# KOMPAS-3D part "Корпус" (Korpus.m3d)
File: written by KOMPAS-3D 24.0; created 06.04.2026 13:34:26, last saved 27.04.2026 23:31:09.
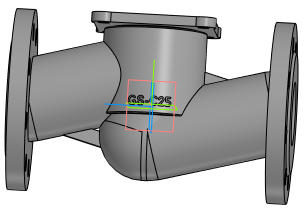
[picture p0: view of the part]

Document properties: Автор: R2D2; Полное имя файла: C:\Работа\ГОТОВЫЕ ИСХОДНИКИ\VSO2130M-F-S Клапан запорный сальниковый DN.ru Ду15-100 Ру40\исходные материалы\DN65\Korpus.m3d

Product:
- Body: Труба / Нестандартная труба / L = 186.9 мм  | qty 1  | 2 such rows
    Материал: Нестандартная труба (density 7856 kg/m3)
    Масса: 24.169128
    Раздел спецификации: Детали
    Примечание: 8,33 кг
    additional columns: Pipeline; 0.085; 0; 0; 0.002; 0.18688; true; 0.04
- Body: Тело 4  | qty 1
    Материал: Нестандартная труба (density 7856 kg/m3)
    Масса: 24.169128
- Body: Тело 5  | qty 1
    Материал: Нестандартная труба (density 7856 kg/m3)
    Масса: 24.169128
- Body: Тело 8  | qty 1
    Материал: Нестандартная труба (density 7856 kg/m3)
    Масса: 24.169128
- Body: Тело 10  | qty 1
    Материал: Нестандартная труба (density 7856 kg/m3)
    Масса: 24.169128
- Body: Тело 11  | qty 1
    Материал: Нестандартная труба (density 7856 kg/m3)
    Масса: 24.169128
- Body: Тело 12  | qty 1
    Материал: Нестандартная труба (density 7856 kg/m3)
    Масса: 24.169128
- Body: Тело 13  | qty 1
    Материал: Нестандартная труба (density 7856 kg/m3)
    Масса: 24.169128
- Part/product: Корпус
    Масса: 6.9

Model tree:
1. Труба:1  (labels: {F703FF30-5BE6-4673-A7F1-8EDA1BE1E2D1}; SHAPEOBJECT3D_ATTR_BUTT; SHAPEOBJECT3D_ATTR_VALID; SHAPEOBJECT3D_ATTR_BUTT_AREA)
     PIPE_R = 3
2. Труба:2  (labels: {F703FF30-5BE6-4673-A7F1-8EDA1BE1E2D1}; SHAPEOBJECT3D_ATTR_BUTT; SHAPEOBJECT3D_ATTR_VALID; SHAPEOBJECT3D_ATTR_BUTT_AREA)
     PIPE_R = 3
3. Колонна
4. Элемент выдавливания:1
     Смещение 1 = -1; Смещение 2 = -5
5. Скругление:17  (with: Ребро.Элемент выдавливания:1)
     Радиус = 1
6. Скругление:18  (with: Ребро.Элемент выдавливания:1)
7. Скругление:24
     Радиус = 1.5
8. Элемент выдавливания:2
     Расстояние 1 = 6
9. Эскиз:4  (with: Грань.Элемент выдавливания:1)
10. Элемент выдавливания:3
     Расстояние 1 = 1.5
11. ОТЛИВКА
12. Скругление:6  (with: Грань.Элемент выдавливания:1)
     Радиус = 2
13. Элемент выдавливания:6  (with: Грань.Элемент выдавливания:1)
     Смещение 1 = 4
14. ЛЕЙБЛ
15. Элемент выдавливания:7  (with: Грань.Элемент выдавливания:1)
     Расстояние 1 = 53.4631; Смещение 1 = 1
16. Dn
17. Pn
18. Стрелочка
19. Элемент выдавливания:10  (with: Грань.Труба:1)
     Расстояние 1 = 43.1666; Смещение 1 = 1
20. Элемент выдавливания:11  (with: Грань.Труба:2)
     Расстояние 1 = 43.4692; Смещение 1 = 1
21. Элемент выдавливания:12  (with: Грань.Элемент выдавливания:1)
     Расстояние 1 = 53.4999; Смещение 1 = 1
22. Материал
23. Элемент выдавливания:13  (with: Грань.Элемент выдавливания:1)
     Расстояние 1 = 52.9898; Смещение 1 = 0.5
24. Фланец верх  (with: Грань.Элемент выдавливания:3)
25. Элемент выдавливания:14
     Расстояние 1 = 10
26. Эскиз:18  (with: Грань.Элемент выдавливания:14)
27. Элемент выдавливания:15
     Расстояние 1 = 0.5
28. Эскиз:19  (with: Грань.Элемент выдавливания:14, Ребро.Элемент выдавливания:14)
29. Элемент выдавливания:16  (with: Грань.Элемент выдавливания:14)
     Расстояние 1 = 0.5; Расстояние 2 = 11; Смещение 2 = 1
30. Фланец
31. Элемент вращения:1
     Угол 1 = 360
32. отвертие во фланце  (with: Грань.Элемент вращения:1)
33. Элемент выдавливания:8
34. Массив по концентрической сетке:2  (with: Элемент выдавливания:8, Эскиз:10, Грань.Элемент вращения:1)  (8 pattern instances)
     Шаг 2 = 360
35. Зеркальный массив:1
36. Экземпляр ( 1 )
37. Экземпляр ( 2 )  (with: Элемент вращения:1, Массив по концентрической сетке:2, Экземпляр ( 1 ), Элемент выдавливания:8)
38. Экземпляр ( 3 )  (with: Элемент выдавливания:8)
39. Экземпляр ( 4 )  (with: Элемент выдавливания:8)
40. Экземпляр ( 5 )  (with: Элемент выдавливания:8)
41. Экземпляр ( 6 )  (with: Элемент выдавливания:8)
42. Экземпляр ( 7 )  (with: Элемент выдавливания:8)
43. Экземпляр ( 8 )  (with: Элемент выдавливания:8)
44. Скругление:25  (with: Ребро.Элемент выдавливания:1)
     Радиус = 1
45. Массив по концентрической сетке:3  (with: Элемент выдавливания:16, Эскиз:19)  (labels: Клапан запорный DN.ru Ду65 Ру40)  (4 pattern instances)
     Шаг 2 = 360

Expressions: DS/2+3; DN/2; LL/2; D1/2+6; D2/2-10
Referenced files in C:\Работа\ГОТОВЫЕ ИСХОДНИКИ\VSO2130M-F-S Клапан запорный сальниковый DN.ru Ду15-100 Ру40\исходные материалы\DN65\: VSO2130M-F-S Клапан запорный DN.ru Ду65 Ру40.a3d
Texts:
  GOST 26.020 Pr3
  var3D
  GS-C25
  смещение колонны вниз
  LL-10
  DN+20
  DS+15
  Труба / Нестандартная труба / L = %s мм
  Ось Y.Начало координат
